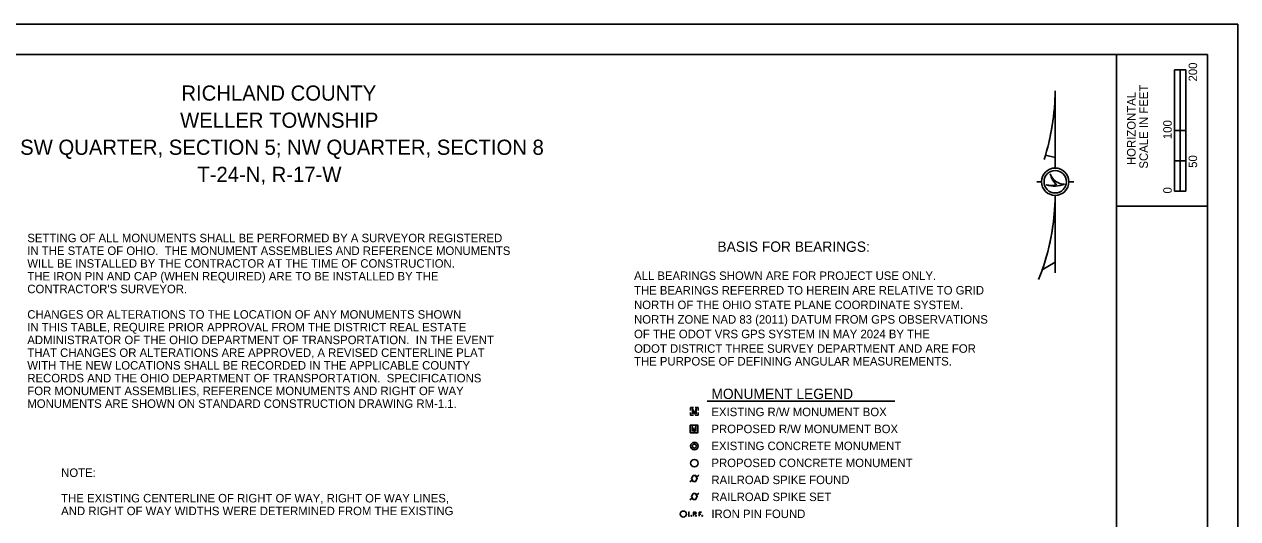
# Model space of a CAD drawing. Extents: x 184845 to 212684, y 341151 to 507086.
# Drawn here: x 210682 to 212684, y 506271 to 507086 of the extents above; entities that cross this region are included whole.
import ezdxf

# ---------------------------------------------------------------- set-up
doc = ezdxf.new("R2010")
doc.units = 0
for name, color, linetype in [('_CIVIL_CONSTRUCTION', 7, 'Continuous'), ('CM_Corridor_Key_Station', 7, 'Continuous'), ('RW_P_Easement_Area', 7, 'Continuous'), ('SV_P_Mon_Cells_Set', 7, 'Continuous')]:
    doc.layers.add(name, color=color, linetype=linetype)

msp = doc.modelspace()

# ---------------------------------------------------------------- linework, layer by layer
at = {"layer": '_CIVIL_CONSTRUCTION'}
for p, q in [((212579.6, 506810.6), (212579.6, 507010.6)), ((212598.3, 507010.6), (212579.6, 507010.6)), ((212579.6, 506910.6), (212579.6, 507010.6)), ((212579.6, 507010.6), (212588.9, 507010.6)), ((212588.9, 507010.6), (212589, 507010.6)), ((212589, 507010.6), (212589, 506910.6)), ((212598.3, 507010.6), (212598.3, 506810.6)), ((212382.9, 506848.6), (212382.9, 506976.1)), ((212589, 506910.6), (212579.6, 506910.6)), ((212598.2, 506910.6), (212588.9, 506910.6)), ((212588.9, 506910.6), (212588.9, 506860.6)), ((212598.2, 506860.6), (212598.2, 506910.6)), ((212367, 506870.1), (212383, 506865.8)), ((212588.9, 506860.6), (212579.6, 506860.6)), ((212579.6, 506860.6), (212579.6, 506810.6)), ((212588.9, 506860.6), (212598.2, 506860.6)), ((212588.9, 506810.6), (212588.9, 506860.6)), ((212352.4, 506826.1), (212360.4, 506826.1)), ((212405.4, 506826.1), (212413.4, 506826.1)), ((212382.9, 506676.1), (212382.9, 506803.6)), ((212598.3, 506810.6), (212579.6, 506810.6)), ((212579.6, 506810.6), (212588.9, 506810.6)), ((212382.9, 506693.6), (212361.5, 506680.7))]:
    msp.add_line(p, q, dxfattribs=at)
for points in [[(212366.9, 506870.2), (212367, 506870.1), (212382.9, 506865.8), (212382.9, 506976.1)], [(212361.5, 506680.7), (212382.9, 506693.6), (212382.9, 506803.6)]]:
    msp.add_lwpolyline(points, dxfattribs=at)
for radius in [22.5, 18.5]:
    msp.add_circle((212382.9, 506826.1), radius, dxfattribs=at)
for centre, radius, start, end in [((211988.7, 506981.6), 394.3, 342.4153, 359.1947), ((211988.7, 506981.6), 394.3, 343.5754, 359.1947), ((212398.7, 506847.4), 25.5, 199.1575, 269.3709), ((212409.6, 506847), 35.8, 192.8556, 227.3141), ((211988.7, 506809.1), 394.3, 338.5054, 359.1947), ((211988.7, 506809.1), 394.3, 340.9936, 359.1947), ((212381.8, 506864), 45.2, 252.4874, 291.486), ((212377.4, 506877.2), 57.1, 260.7277, 277.8734)]:
    msp.add_arc(centre, radius, start, end, dxfattribs=at)
at = {"layer": 'CM_Corridor_Key_Station'}
for p, q in [((211808.9, 506464.1), (212118.1, 506464.1)), ((211787.7, 506447.5), (211787.7, 506447.5)), ((211787.2, 506418.4), (211787.2, 506418.4)), ((211784.3, 506334.3), (211780.3, 506331.3)), ((211795, 506342.3), (211791, 506339.3)), ((211784.3, 506304.6), (211780.3, 506301.6)), ((211795, 506312.6), (211791, 506309.6)), ((211777.8, 506281.5), (211779.5, 506281.5)), ((211777.8, 506281.5), (211779.5, 506281.5)), ((211777.8, 506274.9), (211779.5, 506274.9)), ((211778.7, 506274.9), (211778.7, 506281.5)), ((211786.3, 506278.4), (211789, 506278.4)), ((211795.7, 506274.9), (211795.7, 506281.5)), ((211795.7, 506281.5), (211799.5, 506281.5)), ((211795.7, 506278.3), (211798.4, 506278.3))]:
    msp.add_line(p, q, dxfattribs=at)
for points in [[(211781.4, 506449.1), (211781.4, 506453.7), (211786.1, 506453.7)], [(211786.1, 506441.2), (211781.4, 506441.2), (211781.4, 506445.9)], [(211784.6, 506443.3), (211784.6, 506451.7), (211787.7, 506443.3), (211790.8, 506451.7), (211790.8, 506443.3)], [(211789.2, 506453.7), (211793.9, 506453.7), (211793.9, 506449.1)], [(211793.9, 506445.9), (211793.9, 506441.2), (211789.2, 506441.2)], [(211781, 506424.7), (211793.5, 506424.7), (211793.5, 506412.2), (211781, 506412.2), (211781, 506424.7)], [(211784.1, 506414.3), (211784.1, 506422.6), (211787.2, 506414.3), (211790.3, 506422.6), (211790.3, 506414.3)], [(211789, 506281.5), (211786.3, 506281.5), (211786.3, 506274.9)]]:
    msp.add_lwpolyline(points, dxfattribs=at)
for points in [[(211785.8, 506341.8), (211789.6, 506341.8), (211792.5, 506336.8), (211789.6, 506331.8), (211785.8, 506331.8), (211782.8, 506336.8)], [(211785.8, 506312.1), (211789.6, 506312.1), (211792.5, 506307.1), (211789.6, 506302.1), (211785.8, 506302.1), (211782.8, 506307.1)]]:
    msp.add_lwpolyline(points, close=True, dxfattribs=at)
for centre, radius in [((211787.7, 506390.2), 6.25), ((211787.7, 506390.2), 3.33), ((211787.7, 506362.1), 6.25), ((211769.5, 506278.2), 5), ((211782.7, 506275.3), 0.583), ((211790.3, 506275.3), 0.583), ((211800.5, 506275.3), 0.583)]:
    msp.add_circle(centre, radius, dxfattribs=at)
msp.add_arc((211788.8, 506279.9), 1.62, 278.8803, 81.1197, dxfattribs=at)
at = {"layer": 'RW_P_Easement_Area'}
for p, q in [((212483.9, 504935.6), (212483.9, 507035.6)), ((212483.9, 506785.6), (212633.9, 506785.6))]:
    msp.add_line(p, q, dxfattribs=at)
msp.add_lwpolyline([(209433.9, 507035.6), (212633.9, 507035.6), (212633.9, 504935.6), (209433.9, 504935.6)], close=True, dxfattribs=at)
at = {"layer": 'SV_P_Mon_Cells_Set'}
msp.add_lwpolyline([(209283.9, 504885.6), (212683.9, 504885.6), (212683.9, 507085.6), (209283.9, 507085.6)], close=True, dxfattribs=at)

# ---------------------------------------------------------------- texts
at = {"layer": '_CIVIL_CONSTRUCTION'}
for s, p in [('200', (212616.9, 506991.3)), ('SCALE IN FEET', (212535.7, 506847.7)), ('HORIZONTAL', (212515.4, 506853.5)), ('100', (212575, 506896.3)), ('50', (212616.9, 506848.9)), ('0', (212575, 506806.7))]:
    msp.add_text(s, height=14, rotation=90, dxfattribs=at).set_placement(p)
for s, p in [('              RICHLAND COUNTY             ', (210811.6, 506959.7)), ('              WELLER TOWNSHIP             ', (210809.5, 506915)), ('        SW QUARTER, SECTION 5; NW QUARTER, SECTION 8        ', (210601.4, 506870.4)), ('              T-24-N, R-17-W              ', (210837.9, 506825.7))]:
    msp.add_text(s, height=25, dxfattribs=at).set_placement(p)
at = {"layer": 'CM_Corridor_Key_Station'}
for s, height, p in [('SETTING OF ALL MONUMENTS SHALL BE PERFORMED BY A SURVEYOR REGISTERED', 14, (210687.5, 506726.3)), ('BASIS FOR BEARINGS:', 17, (211825.7, 506710.5)), ('IN THE STATE OF OHIO.  THE MONUMENT ASSEMBLIES AND REFERENCE MONUMENTS', 14, (210687.5, 506705.3)), ('WILL BE INSTALLED BY THE CONTRACTOR AT THE TIME OF CONSTRUCTION.', 14, (210687.5, 506684.3)), ('THE IRON PIN AND CAP (WHEN REQUIRED) ARE TO BE INSTALLED BY THE', 14, (210687.5, 506663.3)), ('ALL BEARINGS SHOWN ARE FOR PROJECT USE ONLY.', 14, (211688.2, 506664.1)), ("CONTRACTOR'S SURVEYOR.", 14, (210687.5, 506642.3)), ('THE BEARINGS REFERRED TO HEREIN ARE RELATIVE TO GRID ', 14, (211688.2, 506640.1)), ('NORTH OF THE OHIO STATE PLANE COORDINATE SYSTEM.     ', 14, (211688.2, 506616.1)), ('CHANGES OR ALTERATIONS TO THE LOCATION OF ANY MONUMENTS SHOWN ', 14, (210687.5, 506600.3)), ('NORTH ZONE NAD 83 (2011) DATUM FROM GPS OBSERVATIONS ', 14, (211688.2, 506592.1)), ('IN THIS TABLE, REQUIRE PRIOR APPROVAL FROM THE DISTRICT REAL ESTATE ', 14, (210687.5, 506579.3)), ('ADMINISTRATOR OF THE OHIO DEPARTMENT OF TRANSPORTATION.  IN THE EVENT', 14, (210687.5, 506558.3)), ('OF THE ODOT VRS GPS SYSTEM IN MAY 2024 BY THE        ', 14, (211688.2, 506568.1)), ('THAT CHANGES OR ALTERATIONS ARE APPROVED, A REVISED CENTERLINE PLAT', 14, (210687.5, 506537.3)), ('ODOT DISTRICT THREE SURVEY DEPARTMENT AND ARE FOR    ', 14, (211688.2, 506544.1)), ('WITH THE NEW LOCATIONS SHALL BE RECORDED IN THE APPLICABLE COUNTY', 14, (210687.5, 506516.3)), ('THE PURPOSE OF DEFINING ANGULAR MEASUREMENTS.', 14, (211688.2, 506523.1)), ('RECORDS AND THE OHIO DEPARTMENT OF TRANSPORTATION.  SPECIFICATIONS', 14, (210687.5, 506495.3)), ('FOR MONUMENT ASSEMBLIES, REFERENCE MONUMENTS AND RIGHT OF WAY', 14, (210687.5, 506474.3)), ('MONUMENT LEGEND', 17, (211815.8, 506467.9)), ('MONUMENTS ARE SHOWN ON STANDARD CONSTRUCTION DRAWING RM-1.1.', 14, (210687.5, 506453.3)), ('EXISTING R/W MONUMENT BOX', 14, (211815.8, 506439.6)), ('PROPOSED R/W MONUMENT BOX', 14, (211815.8, 506411.6)), ('EXISTING CONCRETE MONUMENT', 14, (211815.8, 506383.6)), ('PROPOSED CONCRETE MONUMENT', 14, (211815.8, 506355.6)), ('NOTE:', 14, (210743.3, 506339.4)), ('RAILROAD SPIKE FOUND', 14, (211815.8, 506327.6)), ('THE EXISTING CENTERLINE OF RIGHT OF WAY, RIGHT OF WAY LINES,', 14, (210743.3, 506297.4)), ('RAILROAD SPIKE SET', 14, (211815.8, 506299.6)), ('AND RIGHT OF WAY WIDTHS WERE DETERMINED FROM THE EXISTING', 14, (210743.3, 506276.4)), ('IRON PIN FOUND', 14, (211815.8, 506271.6))]:
    msp.add_text(s, height=height, dxfattribs=at).set_placement(p)

doc.saveas('drawing.dxf')
